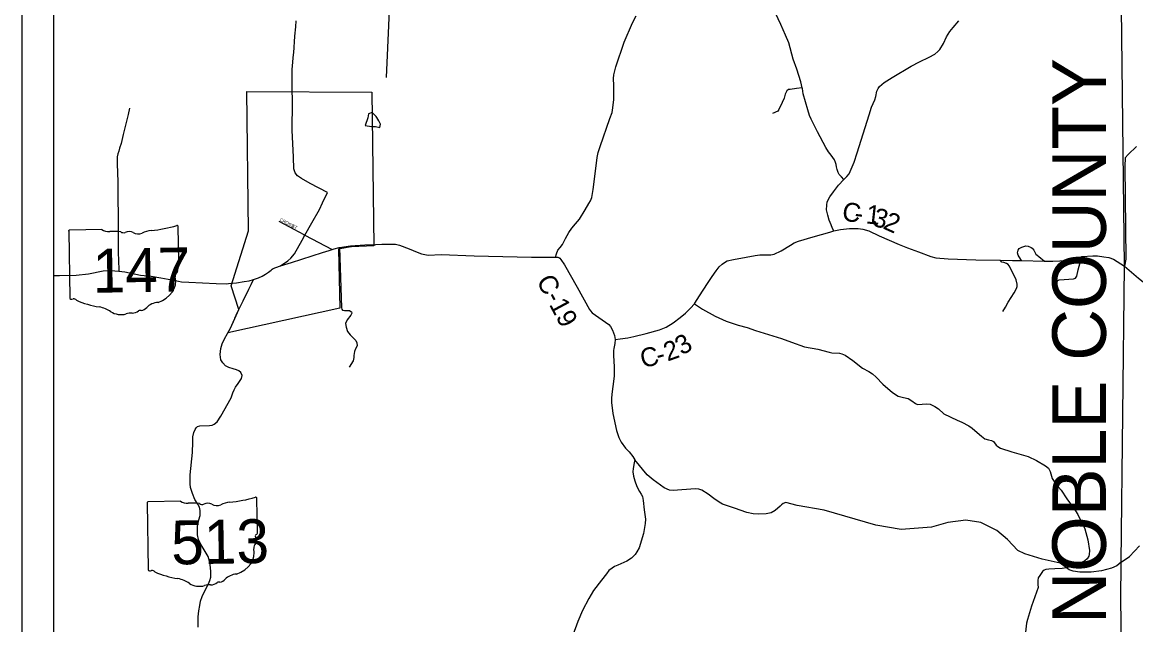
# Model space of a CAD drawing. Extents: x 0 to 2329303, y 0 to 694397.
# Drawn here: x 2 to 5.532, y 16.172 to 18.082 of the extents above; entities that cross this region are included whole.
import ezdxf

# ---------------------------------------------------------------- set-up
doc = ezdxf.new("R2010")
doc.units = 0
for name, color, linetype in [('GM_X_City_Street', 7, 'Continuous'), ('GM_X_City_Street_Text', 7, 'Continuous'), ('GM_X_Corporation', 7, 'Continuous'), ('GM_X_County', 7, 'Continuous'), ('GM_X_County_Road', 7, 'Continuous'), ('GM_X_County_Road_Text', 7, 'Continuous'), ('GM_X_Minor_Lake', 7, 'Continuous'), ('GM_X_State_Route', 7, 'Continuous'), ('GM_X_State_Shield', 7, 'Continuous'), ('GM_X_Township', 7, 'Continuous'), ('GM_X_Township_Road', 7, 'Continuous'), ('GM_X_Township_ROW', 7, 'Continuous'), ('SH_Data', 7, 'Continuous')]:
    doc.layers.add(name, color=color, linetype=linetype)

msp = doc.modelspace()

# ---------------------------------------------------------------- linework, layer by layer
at = {"layer": 'GM_X_City_Street'}
for points in [[(2.8139, 17.4509), (2.8935, 17.409), (2.8936, 17.409)], [(2.8936, 17.409), (2.8966, 17.4074), (2.9831, 17.3619)]]:
    msp.add_lwpolyline(points, dxfattribs=at)
at = {"layer": 'GM_X_Corporation'}
msp.add_lwpolyline([(2.6525, 17.0971), (2.6611, 17.1125), (2.6872, 17.171), (2.6624, 17.2463), (2.7179, 17.4207), (2.7124, 17.8621), (3.1085, 17.8603), (3.1158, 17.3733), (3.0442, 17.3695), (3.0308, 17.3679), (3.0034, 17.3622), (3.0074, 17.1753)], close=True, dxfattribs=at)
at = {"layer": 'GM_X_County_Road'}
for points in [[(3.8808, 17.0765), (3.8965, 17.0786), (3.9213, 17.0816), (3.9405, 17.0854), (3.9788, 17.0949), (4.0216, 17.1068), (4.0423, 17.1154), (4.0647, 17.1292), (4.0874, 17.1458), (4.1037, 17.1595), (4.12, 17.1753), (4.1327, 17.189), (4.139, 17.1995), (4.1604, 17.2321), (4.1759, 17.2571), (4.1886, 17.276), (4.2012, 17.2941), (4.2112, 17.3063), (4.2207, 17.3147), (4.2283, 17.3204), (4.2362, 17.3257), (4.2562, 17.3302), (4.2962, 17.3369), (4.3254, 17.342), (4.3402, 17.3445), (4.3627, 17.3442), (4.3743, 17.3443), (4.3859, 17.3468), (4.4074, 17.3574), (4.4377, 17.3757), (4.4485, 17.3822), (4.4624, 17.3879), (4.5092, 17.4015), (4.5623, 17.4167), (4.5747, 17.4212), (4.5963, 17.4246), (4.6243, 17.428), (4.652, 17.4278), (4.6664, 17.4263), (4.6858, 17.4209), (4.7187, 17.4048), (4.7816, 17.3772), (4.8083, 17.3665), (4.8435, 17.354), (4.8824, 17.3393), (4.8981, 17.335), (4.9378, 17.3315), (5.0251, 17.3292), (5.102, 17.3277), (5.1419, 17.327), (5.1703, 17.3264), (5.2432, 17.3247), (5.2696, 17.3248), (5.3371, 17.3274), (5.3612, 17.3394), (5.396, 17.3415), (5.411, 17.3413), (5.4318, 17.3385), (5.4469, 17.3362), (5.462, 17.3307), (5.4966, 17.3082)], [(3.6915, 17.3376), (3.6987, 17.3374), (3.7019, 17.3366), (3.7052, 17.3342), (3.7084, 17.3302), (3.7202, 17.3126), (3.7599, 17.242), (3.7997, 17.1717), (3.8025, 17.1665), (3.8078, 17.1609), (3.8186, 17.1534), (3.8605, 17.124), (3.8661, 17.1177), (3.8726, 17.1057), (3.8788, 17.0885), (3.8808, 17.0765), (3.8797, 17.0629), (3.877, 17.0476), (3.8759, 17.0408), (3.876, 17.0255), (3.8779, 16.9899), (3.8773, 16.9598), (3.8739, 16.9273), (3.8705, 16.9032), (3.8694, 16.8892), (3.8695, 16.876), (3.8741, 16.8415), (3.8849, 16.7879), (3.8931, 16.7655), (3.9004, 16.7503), (3.9142, 16.7316), (3.9255, 16.7201), (3.9368, 16.7049), (3.9433, 16.6949), (3.9413, 16.6849), (3.9378, 16.6672), (3.9375, 16.656), (3.9388, 16.6432), (3.9429, 16.628), (3.9495, 16.61), (3.958, 16.5944), (3.9637, 16.5856), (3.9673, 16.5781), (3.9698, 16.566), (3.9728, 16.536), (3.9774, 16.5064), (3.9763, 16.4927), (3.9706, 16.461), (3.9569, 16.4156), (3.9501, 16.4028), (3.9442, 16.3939), (3.9323, 16.383), (3.9175, 16.3733), (3.8896, 16.361), (3.8792, 16.3561), (3.8712, 16.3513), (3.8605, 16.3436), (3.8537, 16.3335), (3.8375, 16.3125), (3.8125, 16.2799), (3.797, 16.2549), (3.7773, 16.2167), (3.7623, 16.1817), (3.7466, 16.1383)], [(5.4966, 17.3082), (5.5414, 17.2703), (5.5919, 17.2302), (5.6241, 17.1939), (5.6708, 17.1199), (5.6888, 17.0991), (5.7217, 17.0865), (5.7881, 17.0526), (5.8233, 17.0374), (5.8508, 17.0243), (5.8747, 17.0143)]]:
    msp.add_lwpolyline(points, dxfattribs=at)
at = {"layer": 'GM_X_Minor_Lake'}
for points in [[(3.1246, 17.7803), (3.1228, 17.7829), (3.1105, 17.7963), (3.0986, 17.7917), (3.0961, 17.7788), (3.0883, 17.7543)], [(3.0883, 17.7543), (3.1078, 17.7518), (3.121, 17.7512), (3.1343, 17.7483), (3.1369, 17.7592), (3.1315, 17.7699), (3.1246, 17.7803)]]:
    msp.add_lwpolyline(points, dxfattribs=at)
at = {"layer": 'GM_X_State_Route'}
for points in [[(3.1735, 17.3783), (3.1838, 17.3782), (3.1966, 17.3756), (3.2273, 17.3634), (3.2527, 17.3526), (3.2661, 17.3477), (3.2874, 17.3437), (3.3286, 17.3453), (3.434, 17.341), (3.6154, 17.3377), (3.6915, 17.3376), (3.6953, 17.3473), (3.6995, 17.359), (3.707, 17.368), (3.7144, 17.3769), (3.7236, 17.3963), (3.7337, 17.4158), (3.743, 17.4292), (3.7555, 17.4431), (3.7681, 17.4582), (3.7863, 17.4874), (3.7975, 17.5077), (3.8026, 17.5162), (3.8068, 17.5267), (3.8111, 17.5516), (3.8177, 17.6015), (3.8243, 17.6533), (3.8268, 17.6686), (3.8329, 17.6876), (3.8643, 17.7764), (3.8712, 17.7954), (3.8737, 17.8103), (3.8772, 17.8368), (3.8763, 17.8817), (3.8755, 17.9038), (3.8772, 17.9154), (3.8828, 17.9404), (3.9092, 18.0187), (3.9361, 18.0806), (3.9472, 18.1029)], [(2.8606, 17.9798), (2.8611, 17.9854), (2.8649, 18.0376), (2.8679, 18.0674), (2.8691, 18.0862)], [(2.8565, 17.875), (2.8565, 17.875), (2.8558, 17.9087), (2.8561, 17.9324), (2.8606, 17.9798)], [(2.8195, 17.3093), (2.842, 17.3254), (2.8522, 17.3344), (2.8636, 17.3482), (2.8876, 17.3916), (2.8966, 17.4074), (2.9189, 17.4464), (2.9429, 17.4881), (2.9529, 17.5092), (2.9683, 17.542), (2.9129, 17.5705), (2.8857, 17.5869), (2.8732, 17.5954), (2.8658, 17.6049), (2.8611, 17.6169), (2.8604, 17.6545), (2.8567, 17.7395), (2.8574, 17.8277), (2.8565, 17.875)], [(2.7044, 17.26), (2.7195, 17.2624), (2.7338, 17.2663), (2.7493, 17.2718), (2.7608, 17.2769), (2.7719, 17.2831), (2.7814, 17.2893), (2.7893, 17.2955), (2.7929, 17.2987), (2.796, 17.3008), (2.804, 17.3042), (2.8195, 17.3093), (2.8545, 17.32), (2.952, 17.352), (2.9739, 17.3588), (2.9831, 17.3619), (2.989, 17.3639), (3.0054, 17.3675), (3.0064, 17.3676), (3.0417, 17.3734), (3.0869, 17.3763), (3.1211, 17.3777)], [(3.1211, 17.3777), (3.1212, 17.3777), (3.1409, 17.3785), (3.1721, 17.3783), (3.1735, 17.3783)], [(2.1, 17.2791), (2.1181, 17.2787), (2.1713, 17.2797), (2.2101, 17.2841), (2.2571, 17.2935), (2.2715, 17.2945), (2.294, 17.2938), (2.3064, 17.2926), (2.3253, 17.2908), (2.3751, 17.2805), (2.4084, 17.2768), (2.4394, 17.2718), (2.486, 17.2631), (2.5049, 17.2594), (2.5286, 17.2579), (2.6147, 17.254), (2.6472, 17.253), (2.6544, 17.2536), (2.6547, 17.2537)], [(2.6547, 17.2537), (2.68, 17.256), (2.7044, 17.26)], [(2.6747, 17.1434), (2.683, 17.1623), (2.7007, 17.1991), (2.7188, 17.2359), (2.7265, 17.2501), (2.7338, 17.2663)], [(2.6415, 17.0779), (2.6611, 17.1125), (2.6746, 17.1431), (2.6747, 17.1434)], [(2.5583, 16.1639), (2.5581, 16.1964), (2.5601, 16.2157), (2.563, 16.2326), (2.5659, 16.2467), (2.5712, 16.2616), (2.5793, 16.2786), (2.5909, 16.3009), (2.5955, 16.3114), (2.5985, 16.3223), (2.5981, 16.3399), (2.5965, 16.3623), (2.5939, 16.3731), (2.59, 16.3883), (2.5805, 16.4041), (2.5647, 16.4307), (2.5589, 16.4422), (2.5554, 16.4565), (2.5555, 16.4742), (2.5561, 16.4846), (2.5605, 16.5043), (2.5642, 16.5185), (2.5648, 16.5289), (2.5639, 16.5341), (2.5625, 16.5445), (2.5575, 16.5544), (2.5476, 16.569), (2.5396, 16.5877), (2.5341, 16.6065), (2.5322, 16.6181), (2.5325, 16.6473), (2.5399, 16.7176), (2.5413, 16.7501), (2.5411, 16.7598), (2.5409, 16.7674), (2.5443, 16.7811), (2.5481, 16.7912), (2.5516, 16.7964), (2.5563, 16.8001), (2.5631, 16.8023), (2.5943, 16.8033), (2.6027, 16.8047), (2.6086, 16.8072), (2.6181, 16.8154), (2.6302, 16.8329), (2.6623, 16.8916), (2.6684, 16.9074), (2.6722, 16.9167), (2.676, 16.9248), (2.6854, 16.9366), (2.6955, 16.9524), (2.6977, 16.9621), (2.6931, 16.9712), (2.687, 16.9771), (2.6798, 16.9802), (2.6689, 16.9832), (2.6556, 16.9873), (2.6451, 16.9931), (2.6361, 17.0018), (2.6303, 17.0121), (2.6275, 17.0289), (2.6296, 17.0478), (2.6337, 17.0619), (2.6414, 17.0777), (2.6415, 17.0779)]]:
    msp.add_lwpolyline(points, dxfattribs=at)
at = {"layer": 'GM_X_State_Shield'}
for p, q in [((2.1472, 17.4193), (2.1507, 17.208)), ((2.2524, 17.4247), (2.1505, 17.423)), ((2.4969, 17.3235), (2.495, 17.434)), ((2.4968, 17.3235), (2.4969, 17.3235)), ((2.746, 16.4618), (2.7442, 16.5724)), ((2.3963, 16.5577), (2.3999, 16.3464)), ((2.5016, 16.5631), (2.3997, 16.5613)), ((2.746, 16.4619), (2.746, 16.4618))]:
    msp.add_line(p, q, dxfattribs=at)
for centre, major_axis, start_param, end_param in [((2.1511, 17.4198), (0.00403, 0.00007), 1.712693, 3.28349), ((2.2763, 17.4497), (0.0391, 0.0007), 4.042523, 4.731795), ((2.2917, 17.3067), (0.1404, 0.0024), 1.404758, 1.657858), ((2.3216, 17.4238), (0.0113, 0.0002), 3.836095, 5.185415), ((2.3386, 17.3996), (0.0235, 0.0004), 0.950623, 2.079405), ((2.3683, 17.4336), (0.0282, 0.0005), 4.081561, 5.145723), ((2.4193, 17.363), (0.0742, 0.0012), 1.699011, 2.107814), ((2.3663, 17.7148), (0.369, 0.0062), 4.814394, 5.042369), ((2.4911, 17.4344), (0.00387, 0.00006), 6.141152, 7.989035), ((2.4961, 17.3154), (0.006, 0.0001), 1.883978, 3.671073), ((2.4582, 17.3007), (0.036, 0.0006), 5.934695, 6.695948), ((2.4927, 17.323), (0.00415, 0.00007), 5.05454, 6.418171), ((2.3946, 17.2614), (0.0923, 0.0015), 5.101752, 6.440018), ((2.5115, 17.2775), (0.0262, 0.0004), 2.387724, 3.262537), ((2.1547, 17.2076), (0.00407, 0.00007), 3.00124, 4.508301), ((2.155, 17.2292), (0.031, 0.0005), 4.665946, 4.897461), ((2.1619, 17.196), (0.0112, 0.0002), 0.519207, 1.627899), ((2.3, 17.3882), (0.2665, 0.0045), 4.195997, 4.488961), ((2.2251, 17.1143), (0.0834, 0.0014), 0.823519, 1.323587), ((2.3745, 17.1622), (0.00794, 0.00013), 1.147584, 2.315152), ((2.3706, 17.1912), (0.0298, 0.0005), 4.937069, 5.64225), ((2.4353, 17.1535), (0.0506, 0.0008), 1.647645, 2.488434), ((2.314, 17.1975), (0.0529, 0.0009), 4.026481, 4.996735), ((2.3457, 17.125), (0.0435, 0.0007), 1.495662, 1.94098), ((2.3487, 17.1823), (0.0282, 0.0005), 4.691044, 5.507374), ((2.6155, 16.8531), (0.369, 0.0062), 4.814394, 5.042369), ((2.7403, 16.5728), (0.00387, 0.00006), 6.141152, 7.989035), ((2.4003, 16.5582), (0.00403, 0.00007), 1.712693, 3.28349), ((2.5255, 16.588), (0.0391, 0.0007), 4.042523, 4.731795), ((2.5408, 16.4451), (0.1404, 0.0024), 1.404758, 1.657858), ((2.5707, 16.5621), (0.0113, 0.0002), 3.836095, 5.185415), ((2.5877, 16.538), (0.0235, 0.0004), 0.950623, 2.079405), ((2.6174, 16.572), (0.0282, 0.0005), 4.081561, 5.145723), ((2.6685, 16.5013), (0.0742, 0.0012), 1.699011, 2.107814), ((2.7419, 16.4613), (0.00415, 0.00007), 5.05454, 6.418171), ((2.7607, 16.4158), (0.0262, 0.0004), 2.387724, 3.262537), ((2.7453, 16.4537), (0.006, 0.0001), 1.883978, 3.671073), ((2.7074, 16.4391), (0.036, 0.0006), 5.934695, 6.695948), ((2.6438, 16.3998), (0.0923, 0.0015), 5.101752, 6.440018), ((2.4039, 16.346), (0.00407, 0.00007), 3.00124, 4.508301), ((2.4042, 16.3676), (0.031, 0.0005), 4.665946, 4.897461), ((2.4111, 16.3344), (0.0112, 0.0002), 0.519207, 1.627899), ((2.5492, 16.5266), (0.2665, 0.0045), 4.195997, 4.488961), ((2.6845, 16.2918), (0.0506, 0.0008), 1.647645, 2.488434), ((2.4743, 16.2527), (0.0834, 0.0014), 0.823519, 1.323587), ((2.5631, 16.3359), (0.0529, 0.0009), 4.026481, 4.996735), ((2.5949, 16.2633), (0.0435, 0.0007), 1.495662, 1.94098), ((2.5978, 16.3206), (0.0282, 0.0005), 4.691044, 5.507374), ((2.6237, 16.3006), (0.00794, 0.00013), 1.147584, 2.315152), ((2.6198, 16.3296), (0.0298, 0.0005), 4.937069, 5.64225)]:
    msp.add_ellipse(centre, major_axis=major_axis, ratio=0.8, start_param=start_param, end_param=end_param, dxfattribs=at)
at = {"layer": 'GM_X_Township'}
msp.add_lwpolyline([(5.8223, 14.1123), (5.5, 14.1), (5.5092, 14.6075), (5.4849, 16.2502), (5.4862, 16.3702), (5.4966, 17.3083), (5.484, 18.4012), (5.4927, 19.2711), (5.4941, 19.3381), (5.4896, 19.5547), (5.4893, 19.9096), (5.4898, 20.0261), (5.5032, 20.182), (5.5028, 20.3048), (5.5027, 20.3409), (5.5308, 20.3409), (5.6417, 20.3416)], dxfattribs=at)
at = {"layer": 'GM_X_Township_Road'}
for points in [[(4.606, 17.5838), (4.5987, 17.5918), (4.5919, 17.5997), (4.5882, 17.6057), (4.5849, 17.6149), (4.5833, 17.6233), (4.582, 17.6309), (4.5804, 17.6369), (4.5767, 17.6457), (4.5666, 17.6605), (4.5581, 17.6708), (4.5496, 17.6852), (4.5232, 17.7347), (4.5033, 17.7743), (4.4976, 17.7859), (4.4923, 17.8047), (4.4779, 17.8547), (4.475, 17.8719), (4.4745, 17.874), (4.47, 17.8927), (4.4569, 17.9331), (4.4458, 17.9647), (4.4315, 18.0164), (4.4217, 18.0411), (4.4062, 18.0751), (4.3801, 18.1315)], [(4.5747, 17.4212), (4.5707, 17.428), (4.5658, 17.4392), (4.5597, 17.4544), (4.5556, 17.47), (4.5518, 17.4876), (4.5525, 17.5016), (4.554, 17.5124), (4.562, 17.5281), (4.5734, 17.5447), (4.5897, 17.5652), (4.606, 17.5838), (4.6159, 17.5927), (4.6231, 17.6012), (4.6302, 17.6165), (4.6396, 17.6382), (4.649, 17.6675), (4.6741, 17.7483), (4.687, 17.7889), (4.6937, 17.8129), (4.7049, 17.8365), (4.7082, 17.8462), (4.7112, 17.8631), (4.7149, 17.8721), (4.7199, 17.8787), (4.7343, 17.8907), (4.7601, 17.9068), (4.8197, 17.9428), (4.8461, 17.9561), (4.8772, 17.9712), (4.8949, 17.9814), (4.905, 17.9889), (4.9108, 17.9959), (4.9222, 18.0147), (4.9323, 18.0355), (4.9429, 18.0527), (4.9533, 18.0658), (4.9714, 18.0869)], [(4.4745, 17.874), (4.4565, 17.8722), (4.4357, 17.8692), (4.4313, 17.8684), (4.4258, 17.8651), (4.4198, 17.8543), (4.4167, 17.841), (4.4108, 17.8277), (4.4006, 17.8052), (4.3966, 17.8), (4.3802, 17.793)], [(2.3398, 17.8096), (2.3359, 17.7895), (2.3297, 17.7638), (2.32, 17.726), (2.3142, 17.6975), (2.3087, 17.6827), (2.3059, 17.6738), (2.3036, 17.665), (2.3009, 17.6553), (2.3006, 17.6333), (2.3027, 17.5756), (2.3034, 17.5331), (2.3047, 17.4593), (2.3043, 17.3482), (2.3048, 17.3306), (2.3064, 17.2926)], [(5.5345, 17.6878), (5.5083, 17.6623), (5.4987, 17.6523), (5.4977, 17.6255), (5.5013, 17.3304), (5.4966, 17.3082)], [(3.0064, 17.3676), (3.0128, 17.1763), (3.0136, 17.1727), (3.0156, 17.1695), (3.022, 17.1683), (3.0345, 17.168), (3.0385, 17.1681), (3.0425, 17.1653), (3.0445, 17.1633), (3.0453, 17.1593), (3.0422, 17.1533), (3.0303, 17.1387), (3.0259, 17.1267), (3.0272, 17.1151), (3.0321, 17.1015), (3.0398, 17.0907), (3.0511, 17.0804), (3.058, 17.0724), (3.0616, 17.066), (3.0621, 17.056), (3.0577, 17.0463), (3.0538, 17.0379), (3.0523, 17.0254), (3.0515, 17.019), (3.05, 17.0086), (3.0369, 16.988)], [(5.1703, 17.3264), (5.1623, 17.3381), (5.159, 17.344), (5.1575, 17.3511), (5.1593, 17.3592), (5.1631, 17.3645), (5.1713, 17.3692), (5.184, 17.3728), (5.1912, 17.3719), (5.2006, 17.3678), (5.2038, 17.3659), (5.2092, 17.3593), (5.2156, 17.3471), (5.2194, 17.3432), (5.2255, 17.3394), (5.2432, 17.3247)], [(5.1113, 17.1646), (5.1188, 17.1781), (5.1279, 17.1944), (5.1473, 17.2242), (5.154, 17.2377), (5.1562, 17.2442), (5.1568, 17.2514), (5.1536, 17.2649), (5.1437, 17.2854), (5.1305, 17.3098), (5.1276, 17.3137), (5.123, 17.3172), (5.1142, 17.3201), (5.1081, 17.3215), (5.102, 17.3277)], [(5.2821, 17.2235), (5.2824, 17.2515), (5.2829, 17.2596), (5.2852, 17.2632), (5.2899, 17.2658), (5.3055, 17.2667), (5.3346, 17.2689), (5.3413, 17.2711), (5.3455, 17.2772), (5.3496, 17.2974), (5.3612, 17.3394)], [(4.1327, 17.189), (4.1585, 17.172), (4.1979, 17.1502), (4.2336, 17.134), (4.2717, 17.1219), (4.3002, 17.1141), (4.3267, 17.1047), (4.4082, 17.0792), (4.4403, 17.0674), (4.4813, 17.0533), (4.5238, 17.0452), (4.5603, 17.0358), (4.5687, 17.0343), (4.5927, 17.0329), (4.6004, 17.0309), (4.6108, 17.0266), (4.635, 17.0095), (4.666, 16.9857), (4.6857, 16.975), (4.6969, 16.9675), (4.7086, 16.9568), (4.7297, 16.9349), (4.7606, 16.9079), (4.7785, 16.8965), (4.7959, 16.8919), (4.8104, 16.8887), (4.8226, 16.8811), (4.8337, 16.8731), (4.8402, 16.8705), (4.855, 16.8706), (4.8701, 16.8723), (4.8806, 16.871), (4.8952, 16.8635), (4.907, 16.8563), (4.9235, 16.8408), (4.9658, 16.8198), (4.9812, 16.8139), (5.0032, 16.8018), (5.0138, 16.7945), (5.0291, 16.7814), (5.0431, 16.7691), (5.0541, 16.7614), (5.065, 16.7582), (5.0751, 16.7553), (5.0816, 16.7523), (5.0892, 16.7414), (5.0945, 16.7367), (5.1035, 16.7314), (5.1391, 16.7198), (5.1915, 16.7047), (5.2175, 16.6919), (5.2465, 16.6757), (5.2559, 16.668), (5.2611, 16.6577), (5.2674, 16.6355), (5.2796, 16.6167), (5.2962, 16.5984), (5.3143, 16.5706), (5.3336, 16.5436), (5.3415, 16.5326), (5.3491, 16.5209), (5.371, 16.4755), (5.3806, 16.4406), (5.3853, 16.4067), (5.3845, 16.3947), (5.3838, 16.389), (5.3789, 16.3805), (5.3707, 16.3738), (5.3487, 16.3639), (5.3131, 16.3519), (5.2991, 16.3502), (5.276, 16.3486), (5.2564, 16.3476), (5.2477, 16.3469), (5.2425, 16.3451), (5.2367, 16.3405), (5.2283, 16.3278), (5.2229, 16.3201), (5.2216, 16.312), (5.2224, 16.2992), (5.2228, 16.2892), (5.218, 16.2754), (5.2019, 16.2301), (5.1889, 16.1884), (5.1861, 16.1763), (5.1826, 16.1481)], [(4.4088, 16.5517), (4.4086, 16.5516), (4.4048, 16.548), (4.3885, 16.5343), (4.3757, 16.5266), (4.3605, 16.5237), (4.3369, 16.5223), (4.3185, 16.5237), (4.2992, 16.528), (4.2772, 16.5351), (4.2631, 16.5398), (4.241, 16.548), (4.221, 16.5539), (4.2105, 16.5602), (4.1936, 16.5717), (4.1763, 16.5852), (4.1554, 16.5979), (4.1461, 16.601), (4.1349, 16.6026), (4.0645, 16.5976), (4.0533, 16.5983), (4.0368, 16.6062), (4.0014, 16.6312), (3.982, 16.6467), (3.9433, 16.6949)], [(5.3131, 16.3519), (5.293, 16.3664), (5.2358, 16.3794), (5.1809, 16.396), (5.1581, 16.4072), (5.1258, 16.4418), (5.0913, 16.4699), (5.0412, 16.4963), (4.993, 16.5027), (4.9368, 16.4961), (4.8845, 16.4815), (4.7888, 16.4732), (4.7084, 16.4873), (4.544, 16.5353), (4.4582, 16.5494), (4.4219, 16.5594), (4.414, 16.5565), (4.4088, 16.5517)], [(5.4862, 16.3702), (5.5129, 16.3882), (5.544, 16.4219)], [(5.4862, 16.3702), (5.4728, 16.3587), (5.4559, 16.3506), (5.4238, 16.3423), (5.3907, 16.3384), (5.3547, 16.338), (5.3338, 16.3413), (5.3217, 16.3453), (5.3131, 16.3519)]]:
    msp.add_lwpolyline(points, dxfattribs=at)
at = {"layer": 'GM_X_Township_ROW'}
msp.add_lwpolyline([(3.156, 17.9067), (3.1669, 18.1666)], dxfattribs=at)
at = {"layer": 'SH_Data'}
for points in [[(2, 21), (9, 21), (9, 14), (2, 14)], [(2.1, 20.9), (8.9, 20.9), (8.9, 14.1), (2.1, 14.1)]]:
    msp.add_lwpolyline(points, close=True, dxfattribs=at)

# ---------------------------------------------------------------- texts
at = {"layer": 'GM_X_City_Street_Text'}
for s, rotation, p in [('CROSS', 331.075, (2.8156, 17.4536)), ('ST', 333.435, (2.8537, 17.4332))]:
    msp.add_text(s, height=0.01, rotation=rotation, dxfattribs=at).set_placement(p)
at = {"layer": 'GM_X_County'}
msp.add_text('NOBLE COUNTY', height=0.17, rotation=90, dxfattribs=at).set_placement((5.4378, 16.1747))
at = {"layer": 'GM_X_County_Road_Text'}
for s, rotation, p in [('C', 350.9309, (4.5981, 17.4544)), ('1', 353.62, (4.6745, 17.4445)), ('3', 343.7881, (4.6937, 17.4382)), ('-', 353.1725, (4.6382, 17.4484)), ('2', 335.9421, (4.7274, 17.4292)), ('C-19', 298.2545, (3.63, 17.2622)), ('2', 19.5484, (4.0471, 17.006)), ('3', 30.5897, (4.093, 17.0245)), ('C', 12.4183, (3.9676, 16.9855)), ('-', 14.9304, (4.0184, 16.9976))]:
    msp.add_text(s, height=0.06, rotation=rotation, dxfattribs=at).set_placement(p)
at = {"layer": 'GM_X_State_Shield'}
for s, p in [('147', (2.2238, 17.2241)), ('513', (2.4734, 16.3625))]:
    msp.add_text(s, height=0.13922, rotation=0.961, dxfattribs=at).set_placement(p)

doc.saveas('drawing.dxf')
